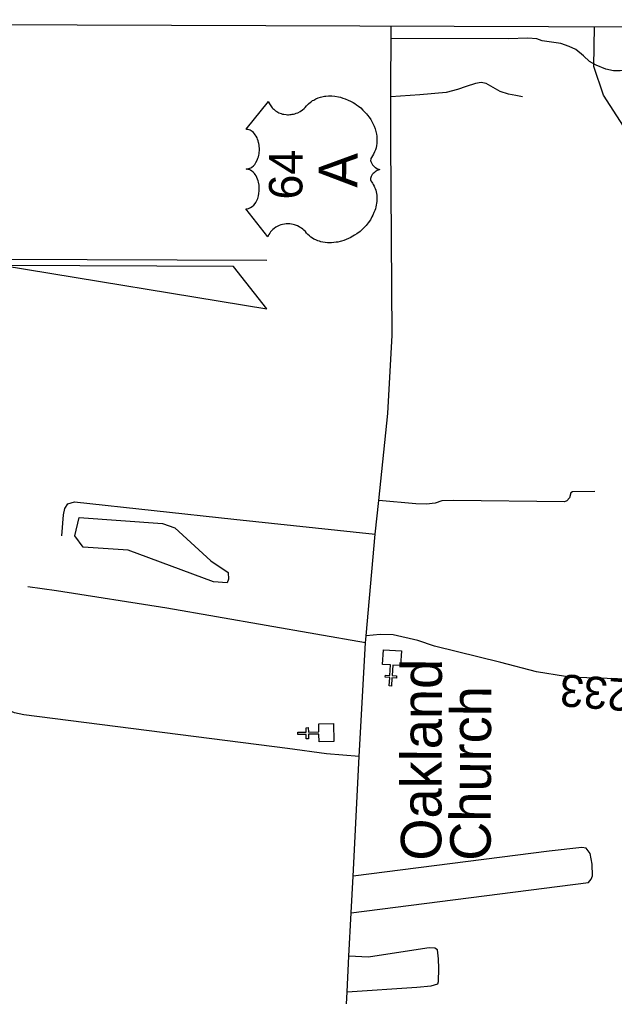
# Model space of a CAD drawing. Extents: x 2364794 to 2387902, y 795230 to 810426.
# Drawn here: x 2366377 to 2366848, y 801786 to 802558 of the extents above; entities that cross this region are included whole.
import ezdxf

# ---------------------------------------------------------------- set-up
doc = ezdxf.new("R2010")
doc.units = 0
for name, color, linetype in [('Default', 7, 'Continuous'), ('Old_Level_4', 7, 'Continuous'), ('Plot Label CELL', 7, 'Continuous'), ('Plot Shape CELL', 7, 'Continuous'), ('User Information Notes CELL', 7, 'Continuous')]:
    doc.layers.add(name, color=color, linetype=linetype)

msp = doc.modelspace()

# ---------------------------------------------------------------- linework, layer by layer
at = {"layer": 'Default'}
for p, q in [((2366556.06, 802471.26), (2366573.64, 802493.17)), ((2366573.64, 802493.17), (2366573.84, 802492.66)), ((2366573.84, 802492.66), (2366574.42, 802491.46)), ((2366605.43, 802491.43), (2366607.04, 802492.8)), ((2366607.04, 802492.8), (2366607.79, 802493.36)), ((2366607.79, 802493.36), (2366608.64, 802493.92)), ((2366608.64, 802493.92), (2366609.51, 802494.44)), ((2366609.51, 802494.44), (2366610.45, 802494.95)), ((2366610.45, 802494.95), (2366611.26, 802495.37)), ((2366611.26, 802495.37), (2366613.15, 802496.13)), ((2366613.15, 802496.13), (2366614.98, 802496.69)), ((2366614.98, 802496.69), (2366615.94, 802496.94)), ((2366615.94, 802496.94), (2366618.1, 802497.35)), ((2366618.1, 802497.35), (2366619.17, 802497.5)), ((2366619.17, 802497.5), (2366621.27, 802497.66)), ((2366621.27, 802497.66), (2366623.81, 802497.66)), ((2366623.81, 802497.66), (2366626.23, 802497.45)), ((2366626.23, 802497.45), (2366629.04, 802496.99)), ((2366629.04, 802496.99), (2366630.73, 802496.61)), ((2366630.73, 802496.61), (2366632.69, 802496.02)), ((2366632.69, 802496.02), (2366634.39, 802495.46)), ((2366634.39, 802495.46), (2366636.89, 802494.44)), ((2366636.89, 802494.44), (2366638.7, 802493.55)), ((2366638.7, 802493.55), (2366640.83, 802492.39)), ((2366574.42, 802491.46), (2366574.97, 802490.51)), ((2366574.97, 802490.51), (2366576.03, 802489)), ((2366576.03, 802489), (2366576.61, 802488.34)), ((2366576.61, 802488.34), (2366577.22, 802487.69)), ((2366577.22, 802487.69), (2366577.87, 802487.09)), ((2366577.87, 802487.09), (2366578.48, 802486.57)), ((2366578.48, 802486.57), (2366579.36, 802485.93)), ((2366579.36, 802485.93), (2366580.24, 802485.35)), ((2366580.24, 802485.35), (2366581.21, 802484.79)), ((2366581.21, 802484.79), (2366582.05, 802484.38)), ((2366596.89, 802484.41), (2366598.8, 802485.4)), ((2366598.8, 802485.4), (2366600.76, 802486.69)), ((2366600.76, 802486.69), (2366601.85, 802487.61)), ((2366601.85, 802487.61), (2366602.79, 802488.51)), ((2366602.79, 802488.51), (2366603.94, 802489.86)), ((2366603.94, 802489.86), (2366604.59, 802490.59)), ((2366604.59, 802490.59), (2366605.43, 802491.43)), ((2366640.83, 802492.39), (2366642.11, 802491.59)), ((2366642.11, 802491.59), (2366643.48, 802490.66)), ((2366643.48, 802490.66), (2366645.06, 802489.5)), ((2366645.06, 802489.5), (2366646.75, 802488.15)), ((2366646.75, 802488.15), (2366648.52, 802486.52)), ((2366648.52, 802486.52), (2366649.83, 802485.2)), ((2366649.83, 802485.2), (2366651.35, 802483.49)), ((2366582.05, 802484.38), (2366583.82, 802483.7)), ((2366583.82, 802483.7), (2366584.93, 802483.37)), ((2366584.93, 802483.37), (2366585.88, 802483.16)), ((2366585.88, 802483.16), (2366587.84, 802482.89)), ((2366587.84, 802482.89), (2366588.77, 802482.83)), ((2366588.77, 802482.83), (2366589.69, 802482.82)), ((2366589.69, 802482.82), (2366590.67, 802482.87)), ((2366590.67, 802482.87), (2366591.6, 802482.96)), ((2366591.6, 802482.96), (2366592.58, 802483.12)), ((2366592.58, 802483.12), (2366593.43, 802483.28)), ((2366593.43, 802483.28), (2366594.49, 802483.55)), ((2366594.49, 802483.55), (2366595.71, 802483.93)), ((2366595.71, 802483.93), (2366596.89, 802484.41)), ((2366651.35, 802483.49), (2366652.21, 802482.45)), ((2366652.21, 802482.45), (2366653.32, 802480.96)), ((2366653.32, 802480.96), (2366654.66, 802478.93)), ((2366654.66, 802478.93), (2366655.81, 802476.93)), ((2366556.71, 802471.24), (2366556.06, 802471.26)), ((2366557.48, 802471.13), (2366556.71, 802471.24)), ((2366558.36, 802470.92), (2366557.48, 802471.13)), ((2366559.19, 802470.56), (2366558.36, 802470.92)), ((2366559.98, 802470.18), (2366559.19, 802470.56)), ((2366560.75, 802469.65), (2366559.98, 802470.18)), ((2366561.8, 802468.74), (2366560.75, 802469.65)), ((2366655.81, 802476.93), (2366656.67, 802475.23)), ((2366656.67, 802475.23), (2366657.32, 802473.72)), ((2366657.32, 802473.72), (2366658.05, 802471.77)), ((2366658.05, 802471.77), (2366658.93, 802468.52)), ((2366562.67, 802467.78), (2366561.8, 802468.74)), ((2366563.32, 802466.97), (2366562.67, 802467.78)), ((2366564.01, 802465.86), (2366563.32, 802466.97)), ((2366564.71, 802464.5), (2366564.01, 802465.86)), ((2366565.17, 802463.44), (2366564.71, 802464.5)), ((2366565.59, 802462.25), (2366565.17, 802463.44)), ((2366565.94, 802460.92), (2366565.59, 802462.25)), ((2366658.93, 802468.52), (2366659.18, 802467.34)), ((2366659.18, 802467.34), (2366659.38, 802465.94)), ((2366659.38, 802465.94), (2366659.51, 802464.63)), ((2366659.57, 802461.65), (2366659.44, 802459.95)), ((2366659.51, 802464.63), (2366659.58, 802463.36)), ((2366659.58, 802463.36), (2366659.57, 802461.65)), ((2366566.15, 802459.92), (2366565.94, 802460.92)), ((2366566.36, 802458.68), (2366566.15, 802459.92)), ((2366566.48, 802457.55), (2366566.36, 802458.68)), ((2366566.43, 802453.08), (2366566.52, 802454.28)), ((2366566.54, 802456.45), (2366566.48, 802457.55)), ((2366566.52, 802454.28), (2366566.55, 802455.25)), ((2366566.55, 802455.25), (2366566.54, 802456.45)), ((2366658.32, 802454.91), (2366657.69, 802453.33)), ((2366658.84, 802456.66), (2366658.32, 802454.91)), ((2366659.2, 802458.34), (2366658.84, 802456.66)), ((2366659.44, 802459.95), (2366659.2, 802458.34)), ((2366563.85, 802445.03), (2366564.74, 802446.77)), ((2366564.74, 802446.77), (2366565.12, 802447.63)), ((2366565.12, 802447.63), (2366565.44, 802448.51)), ((2366565.44, 802448.51), (2366565.78, 802449.62)), ((2366565.78, 802449.62), (2366566.06, 802450.78)), ((2366566.06, 802450.78), (2366566.25, 802451.92)), ((2366566.25, 802451.92), (2366566.43, 802453.08)), ((2366654.63, 802447.78), (2366654.57, 802446.73)), ((2366654.57, 802446.73), (2366654.78, 802445.75)), ((2366654.75, 802448.22), (2366654.63, 802447.78)), ((2366655.17, 802449.01), (2366654.75, 802448.22)), ((2366656.89, 802451.72), (2366655.17, 802449.01)), ((2366657.69, 802453.33), (2366656.89, 802451.72)), ((2366555.97, 802439.82), (2366556.99, 802439.89)), ((2366557.19, 802439.73), (2366555.97, 802439.82)), ((2366556.99, 802439.89), (2366557.63, 802440)), ((2366557.77, 802439.59), (2366557.19, 802439.73)), ((2366557.63, 802440), (2366558.25, 802440.16)), ((2366559.09, 802439.13), (2366557.77, 802439.59)), ((2366558.25, 802440.16), (2366558.92, 802440.42)), ((2366558.92, 802440.42), (2366559.85, 802440.88)), ((2366559.72, 802438.79), (2366559.09, 802439.13)), ((2366560.36, 802438.4), (2366559.72, 802438.79)), ((2366559.85, 802440.88), (2366560.63, 802441.4)), ((2366561.52, 802437.47), (2366560.36, 802438.4)), ((2366560.63, 802441.4), (2366561.79, 802442.38)), ((2366561.79, 802442.38), (2366562.37, 802442.98)), ((2366562.37, 802442.98), (2366562.82, 802443.54)), ((2366562.82, 802443.54), (2366563.85, 802445.03)), ((2366654.78, 802445.75), (2366655.18, 802444.73)), ((2366655.18, 802444.73), (2366655.5, 802444.12)), ((2366655.5, 802444.12), (2366656.03, 802443.31)), ((2366656.03, 802443.31), (2366656.52, 802442.68)), ((2366656.52, 802442.68), (2366657.23, 802441.93)), ((2366657.23, 802441.93), (2366657.83, 802441.41)), ((2366657.83, 802441.41), (2366658.29, 802441.01)), ((2366658.29, 802441.01), (2366659.5, 802440.24)), ((2366659.61, 802438.68), (2366658.83, 802438.22)), ((2366659.5, 802440.24), (2366660.07, 802439.97)), ((2366660.52, 802439.08), (2366659.61, 802438.68)), ((2366660.07, 802439.97), (2366660.81, 802439.68)), ((2366661.89, 802439.42), (2366660.52, 802439.08)), ((2366660.81, 802439.68), (2366661.89, 802439.42)), ((2366562.63, 802436.29), (2366561.52, 802437.47)), ((2366563.22, 802435.47), (2366562.63, 802436.29)), ((2366563.89, 802434.41), (2366563.22, 802435.47)), ((2366564.59, 802433.1), (2366563.89, 802434.41)), ((2366565.08, 802431.91), (2366564.59, 802433.1)), ((2366565.52, 802430.62), (2366565.08, 802431.91)), ((2366654.56, 802432.43), (2366654.51, 802431.78)), ((2366654.51, 802431.78), (2366654.52, 802431.25)), ((2366654.52, 802431.25), (2366654.68, 802430.52)), ((2366654.76, 802433.22), (2366654.56, 802432.43)), ((2366655.01, 802433.87), (2366654.76, 802433.22)), ((2366655.37, 802434.58), (2366655.01, 802433.87)), ((2366655.91, 802435.46), (2366655.37, 802434.58)), ((2366656.59, 802436.29), (2366655.91, 802435.46)), ((2366657.25, 802436.97), (2366656.59, 802436.29)), ((2366658.14, 802437.73), (2366657.25, 802436.97)), ((2366658.83, 802438.22), (2366658.14, 802437.73)), ((2366565.81, 802429.46), (2366565.52, 802430.62)), ((2366566.28, 802426.97), (2366565.81, 802429.46)), ((2366566.44, 802424.71), (2366566.28, 802426.97)), ((2366566.4, 802422.62), (2366566.44, 802424.71)), ((2366654.68, 802430.52), (2366655.4, 802429.52)), ((2366655.4, 802429.52), (2366656.04, 802428.58)), ((2366656.04, 802428.58), (2366656.67, 802427.55)), ((2366656.67, 802427.55), (2366657.32, 802426.33)), ((2366657.32, 802426.33), (2366657.73, 802425.43)), ((2366657.73, 802425.43), (2366658.14, 802424.37)), ((2366658.14, 802424.37), (2366658.55, 802423.12)), ((2366658.55, 802423.12), (2366658.9, 802421.77)), ((2366564.49, 802414.99), (2366565.21, 802416.68)), ((2366565.21, 802416.68), (2366565.76, 802418.58)), ((2366565.76, 802418.58), (2366566.16, 802420.51)), ((2366566.16, 802420.51), (2366566.4, 802422.62)), ((2366658.9, 802421.77), (2366659.17, 802420.38)), ((2366659.17, 802420.38), (2366659.36, 802419.16)), ((2366659.36, 802419.16), (2366659.47, 802417.85)), ((2366659.49, 802415.44), (2366659.39, 802414.28)), ((2366659.47, 802417.85), (2366659.5, 802416.67)), ((2366659.5, 802416.67), (2366659.49, 802415.44)), ((2366555.91, 802408.38), (2366556.82, 802408.43)), ((2366573.33, 802386.35), (2366555.91, 802408.38)), ((2366556.82, 802408.43), (2366557.9, 802408.65)), ((2366557.9, 802408.65), (2366558.45, 802408.82)), ((2366558.45, 802408.82), (2366559.52, 802409.32)), ((2366559.52, 802409.32), (2366560.78, 802410.15)), ((2366560.78, 802410.15), (2366562.02, 802411.3)), ((2366562.02, 802411.3), (2366563.1, 802412.61)), ((2366563.1, 802412.61), (2366563.68, 802413.49)), ((2366563.68, 802413.49), (2366564.49, 802414.99)), ((2366658.31, 802408.46), (2366657.83, 802406.97)), ((2366658.7, 802409.91), (2366658.31, 802408.46)), ((2366659.02, 802411.29), (2366658.7, 802409.91)), ((2366659.27, 802412.95), (2366659.02, 802411.29)), ((2366659.39, 802414.28), (2366659.27, 802412.95)), ((2366654.36, 802399.8), (2366652.57, 802397.24)), ((2366655.62, 802401.99), (2366654.36, 802399.8)), ((2366656.34, 802403.38), (2366655.62, 802401.99)), ((2366657.22, 802405.37), (2366656.34, 802403.38)), ((2366657.83, 802406.97), (2366657.22, 802405.37)), ((2366578.26, 802392.96), (2366577.17, 802392)), ((2366579.6, 802393.89), (2366578.26, 802392.96)), ((2366581.05, 802394.73), (2366579.6, 802393.89)), ((2366582.11, 802395.23), (2366581.05, 802394.73)), ((2366583.57, 802395.77), (2366582.11, 802395.23)), ((2366584.84, 802396.11), (2366583.57, 802395.77)), ((2366586.3, 802396.39), (2366584.84, 802396.11)), ((2366587.82, 802396.55), (2366586.3, 802396.39)), ((2366589.12, 802396.58), (2366587.82, 802396.55)), ((2366590.69, 802396.51), (2366589.12, 802396.58)), ((2366591.95, 802396.34), (2366590.69, 802396.51)), ((2366593.28, 802396.08), (2366591.95, 802396.34)), ((2366594.32, 802395.82), (2366593.28, 802396.08)), ((2366595.8, 802395.31), (2366594.32, 802395.82)), ((2366596.76, 802394.9), (2366595.8, 802395.31)), ((2366598.04, 802394.23), (2366596.76, 802394.9)), ((2366598.91, 802393.72), (2366598.04, 802394.23)), ((2366599.88, 802393.08), (2366598.91, 802393.72)), ((2366600.93, 802392.28), (2366599.88, 802393.08)), ((2366601.68, 802391.62), (2366600.93, 802392.28)), ((2366649.7, 802393.89), (2366647.56, 802391.81)), ((2366650.99, 802395.31), (2366649.7, 802393.89)), ((2366652.57, 802397.24), (2366650.99, 802395.31)), ((2366573.61, 802387.02), (2366573.33, 802386.35)), ((2366574.14, 802388.1), (2366573.61, 802387.02)), ((2366574.82, 802389.21), (2366574.14, 802388.1)), ((2366575.46, 802390.1), (2366574.82, 802389.21)), ((2366576.19, 802391.03), (2366575.46, 802390.1)), ((2366577.17, 802392), (2366576.19, 802391.03)), ((2366602.92, 802390.34), (2366601.68, 802391.62)), ((2366603.79, 802389.27), (2366602.92, 802390.34)), ((2366604.9, 802388.09), (2366603.79, 802389.27)), ((2366606.12, 802386.97), (2366604.9, 802388.09)), ((2366607.22, 802386.11), (2366606.12, 802386.97)), ((2366608.51, 802385.23), (2366607.22, 802386.11)), ((2366609.72, 802384.53), (2366608.51, 802385.23)), ((2366611.17, 802383.8), (2366609.72, 802384.53)), ((2366637.06, 802384.85), (2366635.11, 802384.03)), ((2366638.4, 802385.49), (2366637.06, 802384.85)), ((2366640.53, 802386.65), (2366638.4, 802385.49)), ((2366641.86, 802387.44), (2366640.53, 802386.65)), ((2366643.67, 802388.67), (2366641.86, 802387.44)), ((2366646.17, 802390.59), (2366643.67, 802388.67)), ((2366647.56, 802391.81), (2366646.17, 802390.59)), ((2366612.69, 802383.18), (2366611.17, 802383.8)), ((2366614.06, 802382.71), (2366612.69, 802383.18)), ((2366615.19, 802382.39), (2366614.06, 802382.71)), ((2366616.76, 802382.03), (2366615.19, 802382.39)), ((2366618.59, 802381.73), (2366616.76, 802382.03)), ((2366620.31, 802381.56), (2366618.59, 802381.73)), ((2366621.79, 802381.51), (2366620.31, 802381.56)), ((2366623.57, 802381.53), (2366621.79, 802381.51)), ((2366625.51, 802381.66), (2366623.57, 802381.53)), ((2366627.34, 802381.9), (2366625.51, 802381.66)), ((2366628.68, 802382.14), (2366627.34, 802381.9)), ((2366630.56, 802382.55), (2366628.68, 802382.14)), ((2366631.64, 802382.84), (2366630.56, 802382.55)), ((2366633.33, 802383.38), (2366631.64, 802382.84)), ((2366635.11, 802384.03), (2366633.33, 802383.38)), ((2366650.55, 802065.32), (2366650.93, 802070.75))]:
    msp.add_line(p, q, dxfattribs=at)
for points in [[(2365221.07, 800406.27), (2365228.68, 802558.07), (2367168.28, 802551.22), (2367160.68, 800399.42)], [(2365221.07, 800406.27), (2365228.68, 802558.07), (2367168.28, 802551.22), (2367160.68, 800399.42)], [(2366678.27, 802047.28), (2366672.06, 802047.66), (2366671.54, 802039.35), (2366675.03, 802039.13), (2366674.92, 802037.39), (2366671.43, 802037.6), (2366671.02, 802031.04), (2366669.27, 802031.15), (2366669.68, 802037.71), (2366666.19, 802037.93), (2366666.3, 802039.67), (2366669.79, 802039.46), (2366670.31, 802047.77), (2366664.02, 802048.17), (2366664.74, 802059.79), (2366679, 802058.9)], [(2366613.79, 801986.82), (2366613.64, 801993.05), (2366605.32, 801992.87), (2366605.39, 801989.37), (2366603.65, 801989.33), (2366603.57, 801992.83), (2366597, 801992.69), (2366596.96, 801994.45), (2366603.54, 801994.58), (2366603.46, 801998.08), (2366605.21, 801998.12), (2366605.28, 801994.62), (2366613.61, 801994.8), (2366613.49, 802001.1), (2366625.12, 802001.35), (2366625.42, 801987.07)]]:
    msp.add_lwpolyline(points, close=True, dxfattribs=at)
msp.add_lwpolyline([(2366542.05, 802115.44), (2366541.08, 802112.7), (2366530.28, 802113.5), (2366462.6, 802138.36), (2366426.98, 802140.78), (2366420.55, 802149.77), (2366423.95, 802164.4), (2366489.8, 802159.59), (2366499.62, 802156.04), (2366528.23, 802129.92), (2366541.84, 802120.91), (2366542.05, 802115.44)], dxfattribs=at)
at = {"layer": 'Old_Level_4'}
msp.add_line((2366572.56, 802367.62), (2365980.25, 802369.72), dxfattribs=at)
msp.add_lwpolyline([(2366363.87, 802363.53), (2366572.43, 802329.26), (2366546.12, 802362.89)], close=True, dxfattribs=at)
at = {"layer": 'Plot Label CELL'}
msp.add_line((2366405.88, 802106.35), (2366383.43, 802109.41), dxfattribs=at)
for points in [[(2366886.86, 802552.21), (2366874.6, 802535.38), (2366864.45, 802523.06), (2366861.4, 802520.39), (2366856.4, 802518.39), (2366852.03, 802517.46), (2366846.78, 802517.63), (2366840.65, 802518.89), (2366832.97, 802522.09), (2366827.69, 802524.88), (2366823.06, 802529.42), (2366816.88, 802534.39), (2366811.61, 802536.76), (2366805.02, 802539.09), (2366790.37, 802541.35), (2366785.99, 802542.84), (2366778.98, 802543.42), (2366763.45, 802542.84), (2366670.76, 802542.95)], [(2366774.75, 802497.07), (2366769.49, 802497.96), (2366763.53, 802499.04), (2366756.95, 802501.08), (2366751.52, 802504.43), (2366746.09, 802507.43), (2366742.06, 802508.32), (2366737.5, 802507.46), (2366730.12, 802505.21), (2366723.39, 802502.87), (2366714.23, 802500.37), (2366693.41, 802498.5), (2366670.42, 802496.82)], [(2366831.86, 802184.94), (2366814.38, 802184.56), (2366813.09, 802183.89), (2366811.89, 802179.98), (2366809.77, 802177.36), (2366807.84, 802176.67), (2366720.1, 802177.68), (2366710.97, 802177.53), (2366705.58, 802175.65), (2366698.68, 802174.77), (2366690.43, 802175.15), (2366660.96, 802177.71)], [(2366410.26, 802149.81), (2366411.61, 802166.42), (2366412.67, 802171.46), (2366415.03, 802175.21), (2366420.17, 802176.63), (2366546.22, 802162.94), (2366658.23, 802151.24)], [(2366645.59, 801975.26), (2366619.71, 801977.55), (2366588.75, 801981.6), (2366380.14, 802008.28), (2366372.69, 802009.95), (2366356.43, 802016.37), (2366345.39, 802022.72), (2366331.23, 802036.1), (2366325.46, 802043.14), (2366295.39, 802085.77), (2366288, 802096.33), (2366281.53, 802102.49), (2366276.28, 802106.19), (2366262.88, 802114.22), (2366252.19, 802118.99), (2366245.53, 802121.3), (2366237.99, 802122.55), (2366228.08, 802123.73), (2366211.58, 802123.61), (2366176.91, 802120.14), (2366148.3, 802117.43), (2366010.57, 802104.5), (2365881.19, 802091.98), (2365601.97, 802065.34)], [(2366650.55, 802065.32), (2366493.41, 802092.53), (2366405.88, 802106.35)], [(2366947.33, 802022.4), (2366909.47, 802030.47), (2366881.22, 802034.79), (2366858.02, 802036.54), (2366817.35, 802037.88), (2366808.82, 802038.47), (2366785.8, 802042.4), (2366757.54, 802049.56), (2366705.12, 802062.67), (2366691.98, 802067.02), (2366672.34, 802071.47), (2366662.16, 802071.76), (2366650.93, 802070.75)], [(2366639.18, 801851.8), (2366827.02, 801875.77), (2366829.17, 801878.41), (2366830.23, 801881.03), (2366829.94, 801890.23), (2366828.3, 801898.72), (2366825.01, 801902.84), (2366821.7, 801903.27), (2366795.73, 801900.38), (2366640.69, 801880.74)], [(2366635.98, 801789.2), (2366691.17, 801792.89), (2366702.51, 801794.05), (2366707.78, 801795.43), (2366708.14, 801797.36), (2366708.52, 801807.71), (2366708.38, 801815.43), (2366707.35, 801822.45), (2366705.42, 801823.86), (2366700.86, 801824.05), (2366692.2, 801822.63), (2366652.83, 801816.59), (2366637.22, 801817.52)]]:
    msp.add_lwpolyline(points, dxfattribs=at)
at = {"layer": 'Plot Shape CELL'}
msp.add_line((2366645.59, 801975.26), (2366650.55, 802065.32), dxfattribs=at)
for points in [[(2366650.93, 802070.75), (2366658.23, 802151.24), (2366660.96, 802177.71), (2366668.13, 802246.53), (2366671.5, 802308.43), (2366670.65, 802461.57), (2366670.42, 802496.82), (2366670.83, 802552.98)], [(2366620.55, 801496.5), (2366623.48, 801554.46), (2366630.55, 801687.32), (2366635.98, 801789.2), (2366637.22, 801817.52), (2366639.18, 801851.8), (2366640.69, 801880.74), (2366645.59, 801975.26)]]:
    msp.add_lwpolyline(points, dxfattribs=at)
at = {"layer": 'User Information Notes CELL'}
msp.add_lwpolyline([(2366952.37, 802352.7), (2366854.55, 802473.77), (2366838.92, 802498.22), (2366831.25, 802520.87), (2366831.58, 802552.41)], dxfattribs=at)

# ---------------------------------------------------------------- texts
at = {"layer": 'Default'}
for s, height, p in [('64', 26.483, (2366600.58, 802415.71)), ('A', 30.75, (2366644.16, 802425.08)), ('Oakland', 32.036, (2366710.49, 801892.93)), ('Church', 32.036, (2366749.53, 801892.79))]:
    msp.add_text(s, height=height, rotation=89.79762, dxfattribs=at).set_placement(p)
at = {"layer": 'Plot Label CELL'}
msp.add_text('SR 1233', height=25.362, rotation=175.70042, dxfattribs=at).set_placement((2366937.01, 802030.6))

doc.saveas('drawing.dxf')
